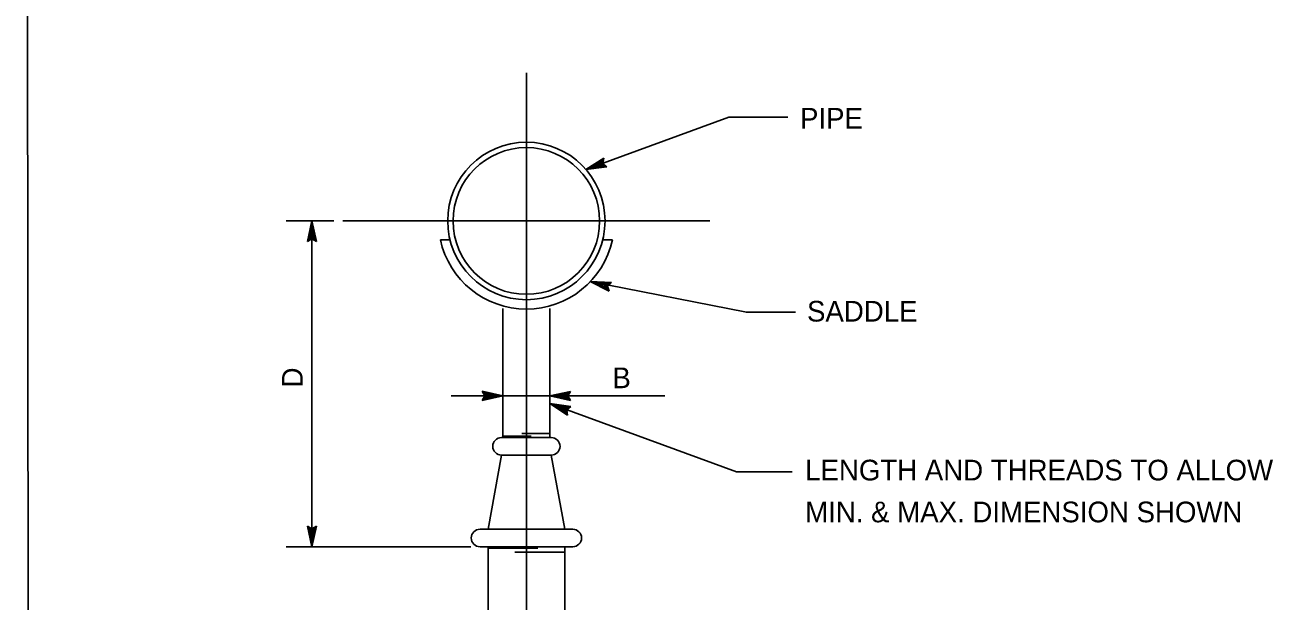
# Model space of a CAD drawing. Extents: x -121933 to -117742, y -103160 to -100084.
# Drawn here: x -121211 to -120848.4, y -101848.5 to -101681.4 of the extents above; entities that cross this region are included whole.
import ezdxf

# ---------------------------------------------------------------- set-up
doc = ezdxf.new("R2010")
doc.units = 0
for name, color, linetype in [('G-MARK', 7, 'Continuous'), ('G-TEXT', 7, 'Continuous'), ('Misc CnstDet(22)', 7, 'Continuous')]:
    doc.layers.add(name, color=color, linetype=linetype)

msp = doc.modelspace()

# ---------------------------------------------------------------- linework, layer by layer
at = {"layer": 'G-MARK'}
for p, q in [((-121121.28, -101738.23), (-121135.14, -101738.23)), ((-121127.64, -101832.76), (-121127.64, -101738.23)), ((-121087.17, -101789.01), (-121072.17, -101789.01)), ((-121025.14, -101789.01), (-121058.5, -101789.01)), ((-121081.44, -101832.76), (-121135.14, -101832.76))]:
    msp.add_line(p, q, dxfattribs=at)
for points in [[(-121048.04, -101723.29), (-121006.55, -101708.15), (-120989.36, -101708.15)], [(-121046.78, -101755.84), (-121001.42, -101764.75), (-120987.14, -101764.72)], [(-121058.5, -101791.19), (-121004.25, -101811.07), (-120988.12, -101811.07)]]:
    msp.add_lwpolyline(points, dxfattribs=at)
at = {"layer": 'G-TEXT'}
for p, q in [((-121048.04, -101723.29), (-121042.86, -101719.99)), ((-121042.27, -101722.24), (-121046.74, -101722.82)), ((-121046.73, -101722.81), (-121042.95, -101720.41)), ((-121045.44, -101722.35), (-121043, -101720.79)), ((-121042.61, -101721.98), (-121045.44, -101722.35)), ((-121044.14, -101721.88), (-121043.1, -101721.21)), ((-121042.9, -101721.71), (-121044.14, -101721.88)), ((-121042.86, -101719.99), (-121043.15, -101721.51)), ((-121043.15, -101721.51), (-121041.94, -101722.5)), ((-121042.86, -101719.99), (-121042.86, -101719.99)), ((-121041.94, -101722.5), (-121048.04, -101723.29)), ((-121048.04, -101723.29), (-121048.04, -101723.29)), ((-121041.94, -101722.5), (-121041.94, -101722.5)), ((-121128.98, -101744.23), (-121127.64, -101738.23)), ((-121128.63, -101744.01), (-121127.64, -101739.61)), ((-121127.64, -101738.23), (-121127.64, -101738.23)), ((-121127.64, -101738.23), (-121126.31, -101744.23)), ((-121127.64, -101739.62), (-121126.67, -101743.99)), ((-121127.64, -101743.43), (-121128.98, -101744.23)), ((-121128.27, -101743.77), (-121127.64, -101740.99)), ((-121127.92, -101743.6), (-121127.65, -101742.37)), ((-121127.65, -101742.37), (-121127.38, -101743.58)), ((-121127.64, -101740.99), (-121127.02, -101743.81)), ((-121126.31, -101744.23), (-121127.64, -101743.43)), ((-121128.98, -101744.23), (-121128.98, -101744.23)), ((-121126.31, -101744.23), (-121126.31, -101744.23)), ((-121041.31, -101758.64), (-121046.78, -101755.84)), ((-121046.78, -101755.84), (-121046.78, -101755.84)), ((-121046.78, -101755.84), (-121040.64, -101756.06)), ((-121041.43, -101758.24), (-121045.45, -101756.19)), ((-121045.44, -101756.19), (-121040.96, -101756.34)), ((-121041.57, -101757.84), (-121044.11, -101756.54)), ((-121044.11, -101756.54), (-121041.22, -101756.64)), ((-121041.65, -101757.46), (-121042.77, -101756.88)), ((-121042.77, -101756.88), (-121041.53, -101756.93)), ((-121040.64, -101756.06), (-121041.75, -101757.14)), ((-121041.75, -101757.14), (-121041.31, -101758.64)), ((-121041.31, -101758.64), (-121041.31, -101758.64)), ((-121040.64, -101756.06), (-121040.64, -101756.06)), ((-121077.37, -101789.01), (-121078.17, -101787.67)), ((-121078.17, -101787.67), (-121078.17, -101787.67)), ((-121078.17, -101787.67), (-121072.17, -101789.01)), ((-121058.5, -101789.01), (-121052.5, -101787.68)), ((-121052.5, -101787.68), (-121053.3, -101789.01)), ((-121052.5, -101787.68), (-121052.5, -101787.68)), ((-121072.17, -101789.01), (-121078.17, -101790.34)), ((-121078.17, -101790.34), (-121077.37, -101789.01)), ((-121078.17, -101790.34), (-121078.17, -101790.34)), ((-121077.96, -101788.02), (-121073.55, -101789.01)), ((-121073.56, -101789.01), (-121077.94, -101789.98)), ((-121074.94, -101789), (-121077.76, -101789.63)), ((-121077.72, -101788.38), (-121074.94, -101789)), ((-121077.55, -101788.73), (-121076.32, -101789)), ((-121076.32, -101789), (-121077.53, -101789.27)), ((-121072.17, -101789.01), (-121072.17, -101789.01)), ((-121052.5, -101790.35), (-121058.5, -101789.01)), ((-121058.5, -101789.01), (-121058.5, -101789.01)), ((-121053.35, -101794.55), (-121058.5, -101791.19)), ((-121058.5, -101791.19), (-121058.5, -101791.19)), ((-121058.5, -101791.19), (-121052.42, -101792.05)), ((-121052.72, -101789.99), (-121057.12, -101789.01)), ((-121057.11, -101789), (-121052.74, -101788.04)), ((-121055.74, -101789.01), (-121052.91, -101788.38)), ((-121052.95, -101789.63), (-121055.74, -101789.01)), ((-121054.36, -101789.01), (-121053.15, -101788.74)), ((-121053.13, -101789.28), (-121054.36, -101789.01)), ((-121053.3, -101789.01), (-121052.5, -101790.35)), ((-121052.5, -101790.35), (-121052.5, -101790.35)), ((-121053.43, -101794.14), (-121057.21, -101791.68)), ((-121057.2, -101791.68), (-121052.76, -101792.3)), ((-121053.52, -101793.72), (-121055.91, -101792.16)), ((-121055.91, -101792.16), (-121053.05, -101792.57)), ((-121053.57, -101793.34), (-121054.62, -101792.65)), ((-121054.62, -101792.65), (-121053.39, -101792.82)), ((-121052.42, -101792.05), (-121053.63, -101793.01)), ((-121053.63, -101793.01), (-121053.35, -101794.55)), ((-121053.35, -101794.55), (-121053.35, -101794.55)), ((-121052.42, -101792.05), (-121052.42, -101792.05)), ((-121127.64, -101832.76), (-121128.97, -101826.76)), ((-121128.97, -101826.76), (-121128.97, -101826.76)), ((-121128.97, -101826.76), (-121127.64, -101827.56)), ((-121127.65, -101831.37), (-121128.61, -101826.99)), ((-121127.64, -101829.99), (-121128.27, -101827.17)), ((-121127.64, -101828.61), (-121127.91, -101827.4)), ((-121127.64, -101827.56), (-121126.3, -101826.76)), ((-121126.3, -101826.76), (-121127.64, -101832.76)), ((-121126.66, -101826.97), (-121127.64, -101831.38)), ((-121127.02, -101827.21), (-121127.64, -101829.99)), ((-121127.36, -101827.38), (-121127.64, -101828.61)), ((-121126.3, -101826.76), (-121126.3, -101826.76)), ((-121127.64, -101832.76), (-121127.64, -101832.76))]:
    msp.add_line(p, q, dxfattribs=at)
at = {"layer": 'Misc CnstDet(22)'}
for p, q in [((-121211.03, -101153.11), (-121209.67, -102136.14)), ((-121065.34, -101955.02), (-121065.34, -101695.26)), ((-121118.66, -101738.23), (-121012.02, -101738.23)), ((-121090.33, -101743.69), (-121087.53, -101743.69)), ((-121043.15, -101743.69), (-121040.34, -101743.69)), ((-121072.17, -101801.12), (-121072.17, -101763.62)), ((-121058.5, -101801.12), (-121058.5, -101763.62)), ((-121072.17, -101787.73), (-121072.17, -101796.51)), ((-121072.17, -101789.01), (-121058.5, -101789.01)), ((-121058.5, -101787.73), (-121058.5, -101796.51)), ((-121072.56, -101801.12), (-121058.11, -101801.12)), ((-121063.97, -101800.73), (-121072.17, -101800.73)), ((-121058.5, -101799.94), (-121066.7, -101799.94)), ((-121072.56, -101806.19), (-121076.47, -101827.68)), ((-121072.56, -101806.19), (-121058.11, -101806.19)), ((-121058.11, -101806.19), (-121054.2, -101827.68)), ((-121078.81, -101827.68), (-121051.86, -101827.68)), ((-121078.81, -101832.76), (-121051.86, -101832.76)), ((-121076.47, -101944.87), (-121076.47, -101832.76)), ((-121062.02, -101833.15), (-121076.47, -101833.15)), ((-121054.2, -101834.32), (-121068.66, -101834.32)), ((-121054.2, -101944.87), (-121054.2, -101832.76))]:
    msp.add_line(p, q, dxfattribs=at)
for radius in [22.85, 21.29]:
    msp.add_circle((-121065.34, -101738.23), radius, dxfattribs=at)
for centre, radius, start, end in [((-121065.34, -101738.23), 25.59, 192.3416, 347.6584), ((-121072.56, -101803.65), 2.54, 90, 270), ((-121058.11, -101803.65), 2.54, 270, 90), ((-121078.81, -101830.22), 2.54, 90, 270), ((-121051.86, -101830.22), 2.54, 270, 90)]:
    msp.add_arc(centre, radius, start, end, dxfattribs=at)

# ---------------------------------------------------------------- texts
for s, p in [('PIPE', (-120985.84, -101711.43)), ('SADDLE', (-120983.8, -101767.43)), ('B', (-121040.35, -101786.76)), ('LENGTH AND THREADS TO ALLOW', (-120984.34, -101813.53)), ('MIN. & MAX. DIMENSION SHOWN', (-120984.34, -101825.68))]:
    msp.add_text(s, height=6, dxfattribs=at).set_placement(p)
msp.add_text('D', height=6, rotation=90, dxfattribs=at).set_placement((-121130.34, -101786.55))

doc.saveas('drawing.dxf')
